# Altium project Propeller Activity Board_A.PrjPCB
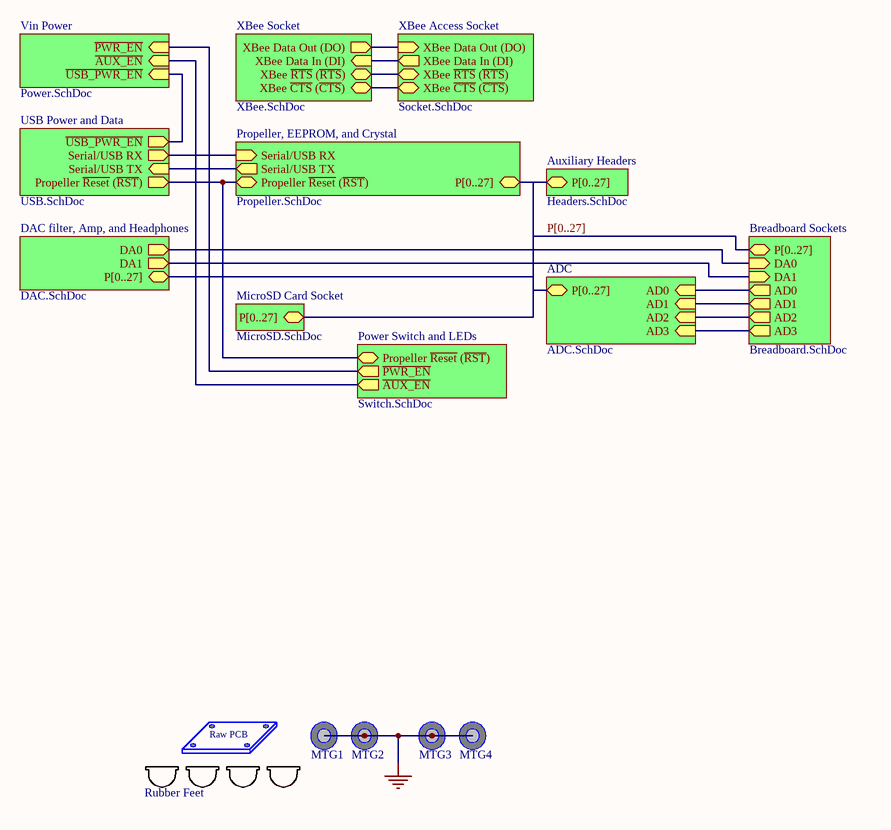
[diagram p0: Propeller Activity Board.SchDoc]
PartNumber: 32910; ProductOwner: Education; ProjectRevision: A; ProjectTitle: Propeller Activity Board
12 sheets, 110 parts. Net scope: hierarchical (ports join the sheet entries above them; power ports are global).
Board files: Propeller Activity Board_A.PcbDoc, Propeller Activity Board_A Array.PcbDoc
Sheets:
  Propeller Activity Board.SchDoc
    Propeller, EEPROM, and Crystal = Propeller.SchDoc
    Vin Power = Power.SchDoc
    Power Switch and LEDs = Switch.SchDoc
    USB Power and Data = USB.SchDoc
    DAC filter, Amp, and Headphones = DAC.SchDoc
    ADC = ADC.SchDoc
    MicroSD Card Socket = MicroSD.SchDoc
    XBee Socket = XBee.SchDoc
    Auxiliary Headers = Headers.SchDoc
    XBee Access Socket = Socket.SchDoc
    Breadboard Sockets = Breadboard.SchDoc

## Sheet Propeller Activity Board.SchDoc: PropBOE
size Letter; CompanyName: Parallax Inc.; Organization: Parallax inc.; Revision: B; SheetNumber: 1; SheetTotal: 12

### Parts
Feet1  Rubber Feet
MTG1  Screw Hole  [MTG_250R-125D]  (value not drawn)  (no BOM)
MTG2  Screw Hole  [MTG_250R-125D]  (value not drawn)  (no BOM)
MTG3  Screw Hole  [MTG_250R-125D]  (value not drawn)  (no BOM)
MTG4  Screw Hole  [MTG_250R-125D]  (value not drawn)  (no BOM)
PCB1  Raw PCB  (value not drawn)  (mechanical)

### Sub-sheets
ADC = ADC.SchDoc: AD0 (in), AD1 (in), AD2 (in), AD3 (in), P[0..27] (bidir)
Auxiliary Headers = Headers.SchDoc: P[0..27] (bidir)
Breadboard Sockets = Breadboard.SchDoc: DA0 (in), DA1 (in), P[0..27] (bidir), AD0 (out), AD1 (out), AD2 (out), AD3 (out)
DAC filter, Amp, and Headphones = DAC.SchDoc: P[0..27] (bidir), DA0 (out), DA1 (out)
MicroSD Card Socket = MicroSD.SchDoc: P[0..27] (bidir)
Power Switch and LEDs = Switch.SchDoc: ~{PWR_EN} (out), ~{AUX_EN} (out), Propeller ~{Reset} (~{RST}) (bidir)
Propeller, EEPROM, and Crystal = Propeller.SchDoc: Serial/USB RX (in), Serial/USB TX (out), P[0..27] (bidir), Propeller ~{Reset} (~{RST}) (bidir)
USB Power and Data = USB.SchDoc: Serial/USB RX (out), Serial/USB TX (in), Propeller ~{Reset} (~{RST}) (out), ~{USB_PWR_EN} (out)
Vin Power = Power.SchDoc: ~{PWR_EN} (in), ~{AUX_EN} (in), ~{USB_PWR_EN} (in)
XBee Access Socket = Socket.SchDoc: XBee ~{CTS} (~{CTS}) (bidir), XBee ~{RTS} (~{RTS}) (bidir), XBee Data In (DI) (out), XBee Data Out (DO) (in)
XBee Socket = XBee.SchDoc: XBee Data Out (DO) (out), XBee Data In (DI) (in), XBee ~{CTS} (~{CTS}) (bidir), XBee ~{RTS} (~{RTS}) (bidir)

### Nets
GND: MTG1.1 MTG2.1 MTG3.1 MTG4.1
~{AUX_EN}: sheet Vin Power/~{AUX_EN}, sheet Power Switch and LEDs/~{AUX_EN}
AD0: sheet ADC/AD0, sheet Breadboard Sockets/AD0
AD1: sheet ADC/AD1, sheet Breadboard Sockets/AD1
AD2: sheet ADC/AD2, sheet Breadboard Sockets/AD2
AD3: sheet ADC/AD3, sheet Breadboard Sockets/AD3
DA0: sheet DAC filter, Amp, and Headphones/DA0, sheet Breadboard Sockets/DA0
DA1: sheet DAC filter, Amp, and Headphones/DA1, sheet Breadboard Sockets/DA1
~{PWR_EN}: sheet Vin Power/~{PWR_EN}, sheet Power Switch and LEDs/~{PWR_EN}
Propeller ~{Reset} (~{RST}): sheet Propeller, EEPROM, and Crystal/Propeller ~{Reset} (~{RST}), sheet Power Switch and LEDs/Propeller ~{Reset} (~{RST}), sheet USB Power and Data/Propeller ~{Reset} (~{RST})
Serial/USB RX: sheet Propeller, EEPROM, and Crystal/Serial/USB RX, sheet USB Power and Data/Serial/USB RX
Serial/USB TX: sheet Propeller, EEPROM, and Crystal/Serial/USB TX, sheet USB Power and Data/Serial/USB TX
~{USB_PWR_EN}: sheet Vin Power/~{USB_PWR_EN}, sheet USB Power and Data/~{USB_PWR_EN}
XBee ~{CTS} (~{CTS}): sheet XBee Socket/XBee ~{CTS} (~{CTS}), sheet XBee Access Socket/XBee ~{CTS} (~{CTS})
XBee Data In (DI): sheet XBee Socket/XBee Data In (DI), sheet XBee Access Socket/XBee Data In (DI)
XBee Data Out (DO): sheet XBee Socket/XBee Data Out (DO), sheet XBee Access Socket/XBee Data Out (DO)
XBee ~{RTS} (~{RTS}): sheet XBee Socket/XBee ~{RTS} (~{RTS}), sheet XBee Access Socket/XBee ~{RTS} (~{RTS})

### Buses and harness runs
bus P[0..27] = sheet ADC/P[0..27] = sheet Auxiliary Headers/P[0..27] = sheet Breadboard Sockets/P[0..27] = sheet DAC filter, Amp, and Headphones/P[0..27] = sheet MicroSD Card Socket/P[0..27] = sheet Propeller, EEPROM, and Crystal/P[0..27]

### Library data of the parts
Feet1 = Rubber Feet: Rubber feet, 4; Manufacturer_PN: SJ-5003 (BLACK); Parallax_PN: 700-00037; Syspro_Desc: PCB Feet, Rubber
MTG1-MTG4 = Screw_Hole: Screw hole for mounting (or high-current connection)
PCB1 = Raw PCB: Raw PCB (For BOM purposes); Parallax_PN: 300-32910; Syspro_Desc: PCB,Raw,Propeller Activity Bd

## Sheet Propeller.SchDoc
size Letter; SheetNumber: 9; SheetTotal: 14
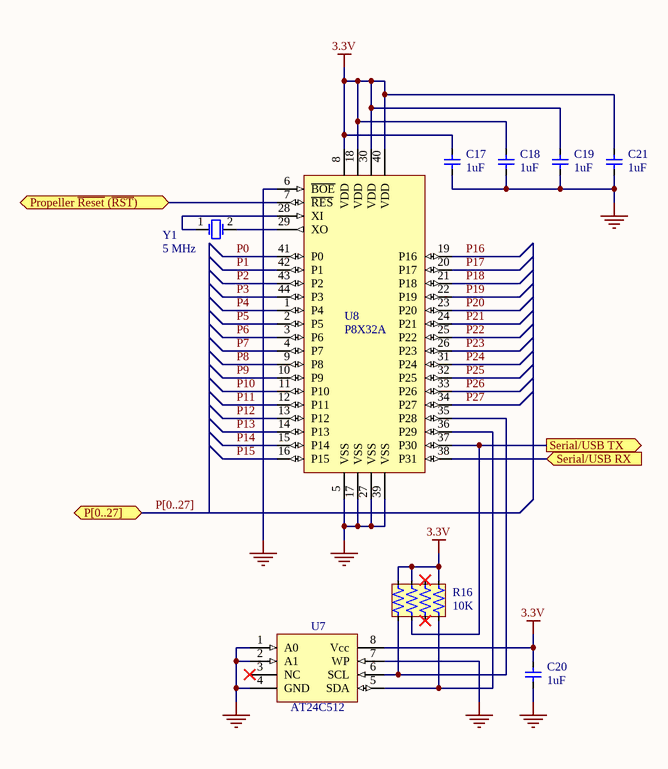
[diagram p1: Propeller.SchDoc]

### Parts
C17  value 1uF  [R/C_0402(1005)]
C18  value 1uF  [R/C_0402(1005)]
C19  value 1uF  [R/C_0402(1005)]
C20  value 1uF  [R/C_0402(1005)]
C21  value 1uF  [R/C_0402(1005)]
R16  value 10K  [R_ARRAY-0402x4]  (hidden comment: Res_Net)
U7  AT24C512  [U_AT24C512K]
U8  P8X32A  [U_P8X32A-Q44]
Y1  value 5 MHz  [Y_HC-49US]  (hidden comment: XTAL)

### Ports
P[0..27] (bidir), Propeller ~{Reset} (~{RST}) (bidir), Serial/USB RX (in), Serial/USB TX (out)

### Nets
3.3V: C17.2 C18.2 C19.2 C20.2 C21.2 R16.1 R16.3 R16.4 U7.8(Vcc) U8.8(VDD) U8.18(VDD) U8.30(VDD) U8.40(VDD)
GND: C17.1 C18.1 C19.1 C20.1 C21.1 U7.1(A0) U7.2(A1) U7.4(GND) U7.7(WP) U8.5(VSS) U8.6(~{BOE}) U8.17(VSS) U8.27(VSS) U8.39(VSS)
P0: U8.41(P0)
P1: U8.42(P1)
P2: U8.43(P2)
P3: U8.44(P3)
P4: U8.1(P4)
P5: U8.2(P5)
P6: U8.3(P6)
P7: U8.4(P7)
P8: U8.9(P8)
P9: U8.10(P9)
P10: U8.11(P10)
P11: U8.12(P11)
P12: U8.13(P12)
P13: U8.14(P13)
P14: U8.15(P14)
P15: U8.16(P15)
P16: U8.19(P16)
P17: U8.20(P17)
P18: U8.21(P18)
P19: U8.22(P19)
P20: U8.23(P20)
P21: U8.24(P21)
P22: U8.25(P22)
P23: U8.26(P23)
P24: U8.31(P24)
P25: U8.32(P25)
P26: U8.33(P26)
P27: U8.34(P27)
Propeller ~{Reset} (~{RST}): U8.7(~{RES}) ; port Propeller ~{Reset} (~{RST})
Serial/USB RX: U8.38(P31) ; port Serial/USB RX
Serial/USB TX: R16.6 U8.37(P30) ; port Serial/USB TX
NetR16_5: R16.5 U7.6(SCL) U8.35(P28)
NetR16_8: R16.8 U7.5(SDA) U8.36(P29)
NetU8_28: U8.28(XI) Y1.1(OSC1)
NetU8_29: U8.29(XO) Y1.2(OSC2)

Not connected (* = marked no-connect by the designer): R16 2* 7*; U7 3(NC)*

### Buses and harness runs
bus P[0..27] = port P[0..27]

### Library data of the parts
C17-C21 = Capacitor: Cap, 1uF, 0402, X5R; Manufacturer_PN: C1005X5R1A105M050BB; Syspro_Desc: CAP-CER,1.0uF,X5R,10V,0402; Parallax_PN: 200-11511
R16 = Res_Net: Resistor Network; Manufacturer_PN: RAVF104DJT10K0; Syspro_Desc: RES-NTWK,10K,5%,0804; Parallax_PN: 179-10000
U7 = AT24C512: 512K (65,536 x 8) I2C EEPROM; Manufacturer: Paralax Inc.; Manufacturer_PN: M24512-RDW6TP; Est_Cost: 1.025; Parallax_PN: 602-10001; MaxOpTempC: 125; MinOpTempC: -55; Syspro_Desc: IC SRL EEPROM 512K 2.7V
U8 = P8X32A-Q44: Manufacturer: Paralax Inc.; Est_Cost: 2.29216; MaxOpTempC: 125; MinOpTempC: -55; Syspro_Desc: IC-P8X32A-Q44 (QFP)
Y1 = XTAL: Crystal Oscillator; Manufacturer_PN: ECS-50-20-4X; Parallax_PN: 251-05000; Syspro_Desc: XTAL,HC-49US,5MHz,20pF,TH

## Sheet Power.SchDoc
size Letter; SheetNumber: 8; SheetTotal: 14; PageSetup: Record=PageOptions|CenterHorizontal=True|CenterVertical=True|PrintScale=0.98|XCorrection=1.00|YCorrection=1.00|PrintKind=1|BorderSize=5000000|LeftOffset=0|BottomOffset=0|Orientation=2|PaperLength=1000|PaperWidth=1000|Scale=100|PaperSource=7|PrintQuality=-4|MediaType=1|DitherType=10|PaperKind=Letter|PrintScaleMode=1
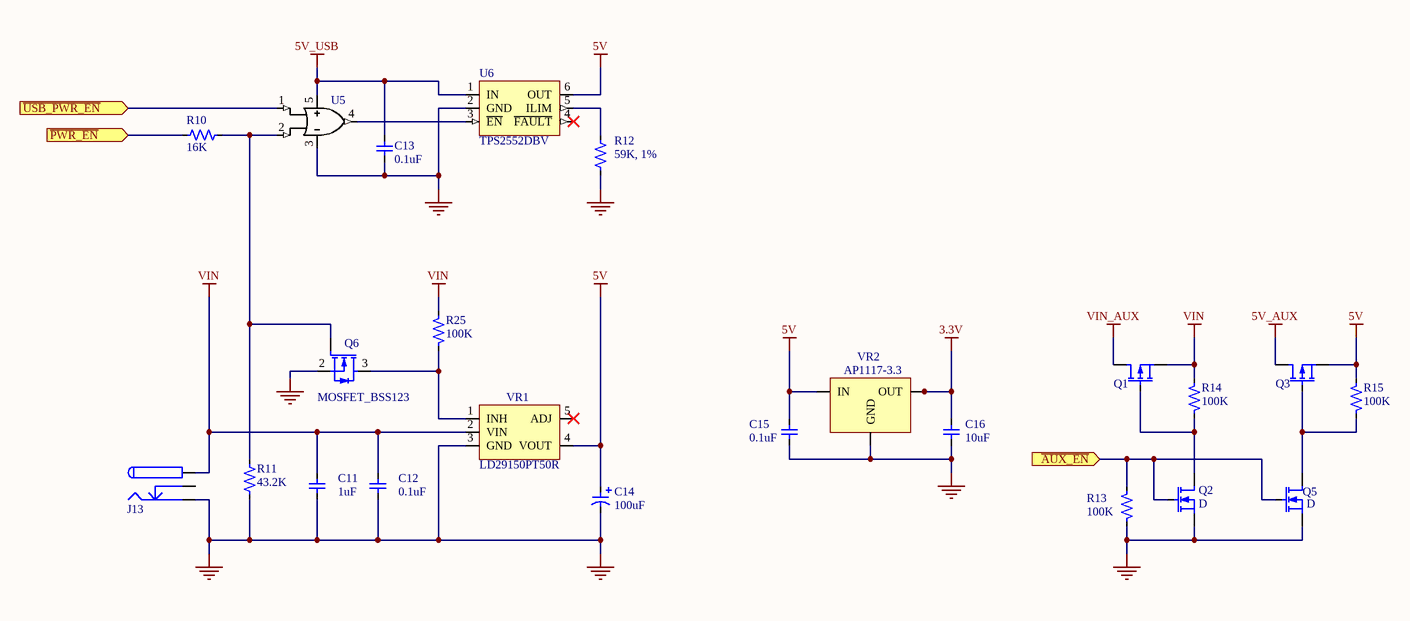
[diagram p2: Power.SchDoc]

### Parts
C11  value 1uF  [R/C_0402(1005)]  (hidden comment: Capacitor)
C12  value 0.1uF  [R/C_0402(1005)]  (hidden comment: Capacitor)
C13  value 0.1uF  [R/C_0603(1608)]  (hidden comment: Capacitor)
C14  value 100uF  [C_6.3x7.7_25V-ALUM]  (hidden comment: Cap_Pol)
C15  value 0.1uF  [R/C_0603(1608)]  (hidden comment: Capacitor)
C16  value 10uF  [R/C_0805(2012)]  (hidden comment: Capacitor)
J13  PWR2.1  [J_CON 2.1mm PWR]  (value not drawn)
Q1  D  [Q_SOT23]  (value not drawn)
Q2  D  [Q_SOT23]
Q3  D  [Q_SOT23]  (value not drawn)
Q5  D  [Q_SOT23]
Q6  MOSFET_BSS123  [Q_SOT23]
R10  value 16K  [R/C_0402(1005)]  (hidden comment: Resistor)
R11  value 43.2K  [R/C_0402(1005)]  (hidden comment: Resistor)
R12  value 59K, 1%  [R/C_0402(1005)]  (hidden comment: Resistor)
R13  value 100K  [R/C_0402(1005)]  (hidden comment: Resistor)
R14  value 100K  [R/C_0402(1005)]  (hidden comment: Resistor)
R15  value 100K  [R/C_0402(1005)]  (hidden comment: Resistor)
R25  value 100K  [R/C_0402(1005)]  (hidden comment: Resistor)
U5  74LVC1G32  [SOT323-5L]  (value not drawn)
U6  TPS2552DBV  [U_TPS2553DBVT]
VR1  LD29150PT50R  [VR_PPAK]
VR2  AP1117-3.3  [VR_SOT223]

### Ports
~{AUX_EN} (in), ~{PWR_EN} (in), ~{USB_PWR_EN} (in)

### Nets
3.3V: C16.2 VR2.OUT_1(OUT) VR2.OUT_2(OUT)
5V: C14.1(Positive) C15.1 Q3.2(Source) R15.2 U6.6(OUT) VR1.4(VOUT) VR2.IN
5V_AUX: Q3.3(Drain)
5V_USB: C13.1 U5.5(VCC) U6.1(IN)
GND: C11.2 C12.2 C13.2 C14.2(Negative) C15.2 C16.1 J13.- Q2.2(Source) Q5.2(Source) Q6.2(S) R11.1 R12.1 R13.1 U5.3(GND) U6.2(GND) VR1.3(GND) VR2.GND
VIN: C11.1 C12.1 J13.+ Q1.2(Source) R14.1 R25.1 VR1.2(VIN)
VIN_AUX: Q1.3(Drain)
~{AUX_EN}: Q2.1(Gate) Q5.1(Gate) R13.2 ; port ~{AUX_EN}
~{PWR_EN}: R10.2 ; port ~{PWR_EN}
~{USB_PWR_EN}: U5.1(A) ; port ~{USB_PWR_EN}
NetQ1_1: Q1.1(Gate) Q2.3(Drain) R14.2
NetQ3_1: Q3.1(Gate) Q5.3(Drain) R15.1
NetQ6_1: Q6.1(G) R10.1 R11.2 U5.2(B)
NetQ6_3: Q6.3(D) R25.2 VR1.1(INH)
NetR12_2: R12.2 U6.5(ILIM)
NetU5_4: U5.4(Y) U6.3(~{EN})

Not connected (* = marked no-connect by the designer): J13 S; U6 4(~{FAULT})*; VR1 5(ADJ)*

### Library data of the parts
C11 = Capacitor: Manufacturer_PN: C1005X5R1A105M050BB; Syspro_Desc: CAP-CER,1.0uF,X5R,10V,0402; Parallax_PN: 200-11511
C12 = Capacitor: Manufacturer_PN: CC0402ZRY5V8BB104; Syspro_Desc: CAP-CER,0.1uF,Y5R,25V,0402; Parallax_PN: 200-11509
C13 C15 = Capacitor: Manufacturer_PN: GRM188F51E104ZA01D; Syspro_Desc: CAP-CER,0.1uF,20%,25V,Y5V,0603; Parallax_PN: 213-01040
C14 = Cap_Pol: Polarized Capacitor; Manufacturer_PN: EMVA250ADA101MF80G; Syspro_Desc: CAP-ALUM,100uF,25V,20%,6.3mm; Parallax_PN: 200-11518
C16 = Capacitor: Manufacturer_PN: C2012Y5V1C106Z; Est_Cost: 0.02843; Syspro_Desc: CAP-CER,10uF,16V,0805; Parallax_PN: 200-11503
J13 = PWR2.1: Low Voltage Power Supply Connector; Manufacturer: Paralax Inc.; Manufacturer_PN: RAPC722X; Parallax_PN: 452-00007; Est_Cost: 0.6822; Syspro_Desc: Connector, PWR, 2.1mm
Q1 Q3 = MOSFET-P: MOSFET P-ch; Manufacturer_PN: DMP2305U; Syspro_Desc: MOSFET,P-CH,20V,4.2A,SOT-23; Parallax_PN: 500-10025
Q2 Q5 = MOSFET-N: MOSFET N-ch; Manufacturer_PN: 2N7002-TP; Syspro_Desc: FET-NCH,60V,115mA,SOT-23; Parallax_PN: 500-10015
Q6 = MOSFET-N DUAL: BSS123; Manufacturer_PN: 74LVC1G58GW,125; Parallax_PN: 500-10016; Syspro_Desc: IC-MOSFET, BSS123, SOT-23
R10 = Resistor: Manufacturer_PN: ERJ-2GEJ163X; Syspro_Desc: RES,16k,5%,0402; Parallax_PN: 150-12022
R11 = Resistor: Manufacturer_PN: RC0402FR-0743K2L; Syspro_Desc: RES,43.2K,1%,0402; Parallax_PN: 172-16007
R12 = Resistor: Manufacturer_PN: RMCF0402FT59K0; Syspro_Desc: RES,59k,1%,0402; Parallax_PN: 172-16005
R13-R15 R25 = Resistor: Manufacturer_PN: RMCF0402JT100K; Syspro_Desc: RES,100K,5%,0402; Parallax_PN: 173-01040
U5 = 74LVC1G32: OR gate; Manufacturer: Any; Est_Cost: 0.0801; Parallax_PN: 604-10026; MaxOpTempC: 125; MinOpTempC: -40; Syspro_Desc: IC-SNGL 2-INPT,OR GATE,SOT-353
U6 = TPS2552DBVR: Current-limited Power-distribution Switch; Manufacturer: Texas Instruments Inc.; Est_Cost: 1.28; Parallax_PN: 400-10008; MaxOpTempC: 150; MinOpTempC: -40; Syspro_Desc: IC-PWR DIST SWITCH,ADJ,SOT23-6
VR1 = VR_LD29150: Parallax_PN: 601-00523; Syspro_Desc: IC REG LDO 5V 1.5A PPAK
VR2 = AP1117-3.3: 3.3V 1A LDO; pin to pad: GND>1 IN>3 OUT_1>2 OUT_2>4; Manufacturer: Any; Est_Cost: 0.1558; Parallax_PN: 601-10504; MaxOpTempC: 125; MinOpTempC: 0; Syspro_Desc: IC-REG,LDO,1.0A,3.3V,SOT-223

## Sheet Switch.SchDoc
size Letter; SheetNumber: 11; SheetTotal: 14
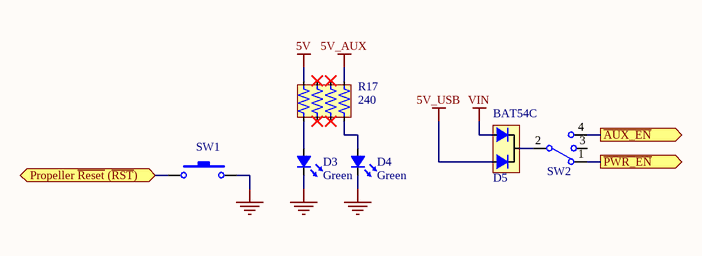
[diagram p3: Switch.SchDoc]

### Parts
D3  Color: Green  [D_LED1608-0603]  (hidden comment: LED)
D4  Color: Green  [D_LED1608-0603]  (hidden comment: LED)
D5  Manufacturer_PN: BAT54C  [Q_SOT23]  (hidden comment: Diode Pair, CC)
R17  value 240  [R_ARRAY-0402x4]  (hidden comment: Res_Net)
SW1  SW-PB  [SW_SMD_J-bend]  (value not drawn)
SW2  Power selection switch  [SWI_OS103011MS8QP1]  (value not drawn)

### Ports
Propeller ~{Reset} (~{RST}) (bidir), ~{AUX_EN} (out), ~{PWR_EN} (out)

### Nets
5V: R17.4
5V_AUX: R17.1
5V_USB: D5.2(Anode)
GND: D3.2(Cathode) D4.2(Cathode) SW1.2
VIN: D5.1(Anode)
~{AUX_EN}: SW2.4(NC2) ; port ~{AUX_EN}
~{PWR_EN}: SW2.1(NC1) ; port ~{PWR_EN}
Propeller ~{Reset} (~{RST}): SW1.1 ; port Propeller ~{Reset} (~{RST})
NetD3_1: D3.1(Anode) R17.5
NetD4_1: D4.1(Anode) R17.8
NetD5_3: D5.3(Cathode) SW2.2(COMMON1)

Not connected (* = marked no-connect by the designer): R17 2* 3* 6* 7*; SW2 3(NO1)

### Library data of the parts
D3 D4 = LED: Manufacturer_PN: LTST-C191KGKT; Parallax_PN: 350-10003; Syspro_Desc: LED 0603, Green Clear; Rotation_Offset: 180
D5 = Diode_Pair_CC: Diode Pair, Common Cathode; Syspro_Desc: DIO-CC,BAT54C,200mA,30V; Parallax_PN: 501-10023; Rotation_Offset: 90
R17 = Res_Net: Resistor Network; Manufacturer_PN: CRA4S8240TR-ND; Syspro_Desc: RES-NTWK,240,5%,0804; Parallax_PN: 179-10006
SW1 = SW-PB: Push-button switch; Manufacturer: C&K Components; Manufacturer_PN: PTS645SM43SMTR LFS; Parallax_PN: 400-10002; Syspro_Desc: SW-PB,Tactile,Blue,SMD; Est_Cost: 0.137; Rotation_Offset: 0
SW2 = SW-SP3T: Switch SP3T; Manufacturer: C&K Components; Manufacturer_PN: 611-OS103011MS8QP1; Est_Cost: 0.249; Parallax_PN: 400-10007; Syspro_Desc: SWI,SP3T Slide,0.1A,12V,TH

## Sheet USB.SchDoc
size Letter; DrawnBy: T.B.; SheetNumber: 3; SheetTotal: 5; DocumentDescription: Schematic, USB Connection; SheetSize: Letter; ProjectRevision: A; ProjectDescription: Propeller Activity Board; ProjectTitle: Propeller Activity Board; PartNumber: 32910
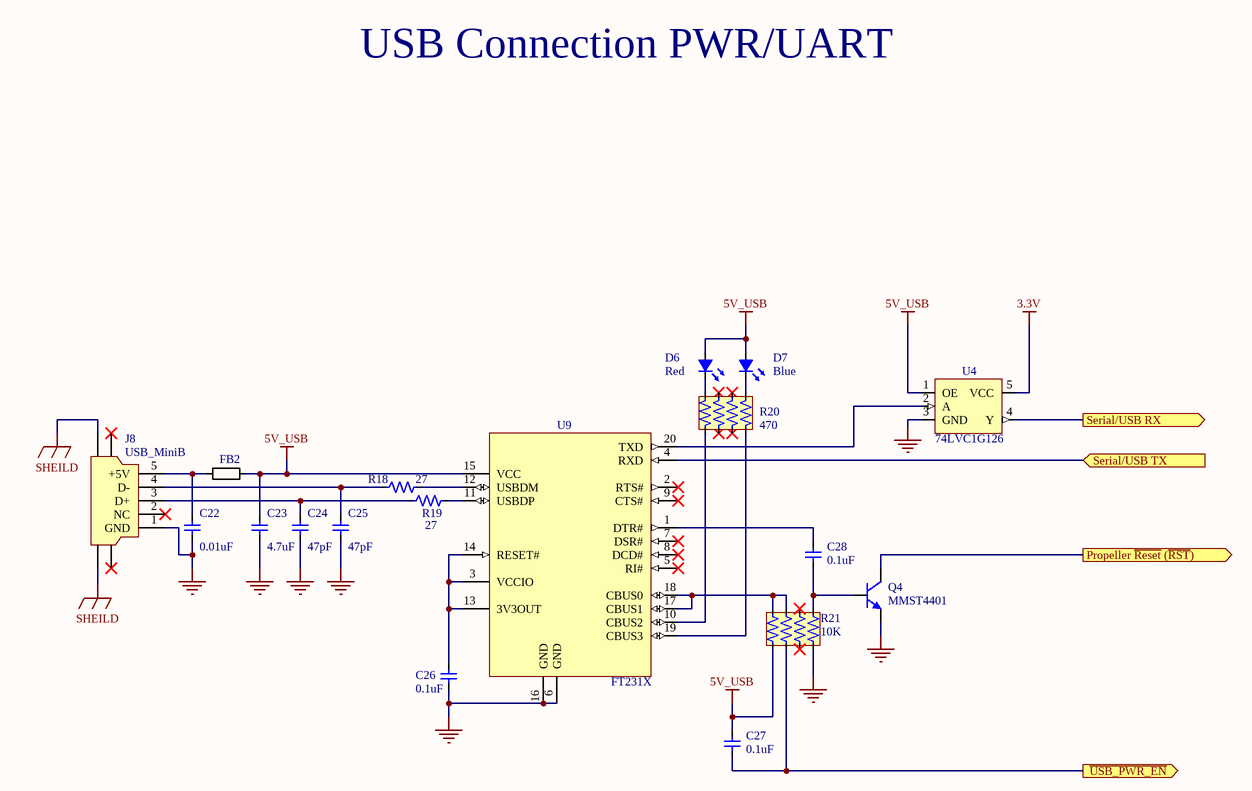
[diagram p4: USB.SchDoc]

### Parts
C22  value 0.01uF  [R/C_0603(1608)]  (hidden comment: Capacitor)
C23  value 4.7uF  [R/C_0603(1608)]  (hidden comment: Capacitor)
C24  value 47pF  [R/C_0603(1608)]  (hidden comment: Capacitor)
C25  value 47pF  [R/C_0603(1608)]  (hidden comment: Capacitor)
C26  value 0.1uF  [R/C_0603(1608)]  (hidden comment: Capacitor)
C27  value 0.1uF  [R/C_0603(1608)]
C28  value 0.1uF  [R/C_0603(1608)]  (hidden comment: Capacitor)
D6  Color: Red  [LED1608-0603]  (hidden comment: LED)
D7  Color: Blue  [LED1608-0603]  (hidden comment: LED)
FB2  Ferrite Bead  [CD1608-0603]  (value not drawn)
J8  USB_MiniB  [J_USB MINI B-TH_SD-51387-3]
Q4  Manufacturer_PN: MMST4401  [Q_SOT323]  (hidden comment: BJT_NPN)
R18  value 27  [R/C_0603(1608)]  (hidden comment: Resistor)
R19  value 27  [R/C_0603(1608)]  (hidden comment: Resistor)
R20  value 470  [R_ARRAY-0402x4]  (hidden comment: Res_Net)
R21  value 10K  [R_ARRAY-0402x4]  (hidden comment: Res_Net)
U4  74LVC1G126  [SOT353-5AN]
U9  FT231X  [U_SSOP20_FT231XS]

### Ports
Propeller ~{Reset} (~{RST}) (out), Serial/USB RX (out), Serial/USB TX (in), ~{USB_PWR_EN} (out)

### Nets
3.3V: U4.5(VCC)
5V_USB: C23.2 C27.2 D6.A(Anode) D7.A(Anode) FB2.1 R21.5 U4.1(OE) U9.15(VCC)
GND: C22.1 C23.1 C24.1 C25.1 C26.1 J8.1(GND) Q4.E(Emitter) R21.8 U4.3(GND) U9.6(GND) U9.16(GND)
SHEILD: J8.7(Sh) J8.8(Sh)
Propeller ~{Reset} (~{RST}): Q4.C(Collector) ; port Propeller ~{Reset} (~{RST})
Serial/USB RX: U4.4(Y) ; port Serial/USB RX
Serial/USB TX: U9.4(RXD) ; port Serial/USB TX
~{USB_PWR_EN}: C27.1 R21.6 ; port ~{USB_PWR_EN}
NetC22_2: C22.2 FB2.2 J8.5(+5V)
NetC24_2: C24.2 J8.3(D+) R19.2
NetC25_2: C25.2 J8.4(D-) R18.2
NetC26_2: C26.2 U9.3(VCCIO) U9.13(3V3OUT) U9.14(RESET#)
NetC28_1: C28.1 Q4.B(Base) R21.1
NetC28_2: C28.2 U9.1(DTR#)
NetD6_K: D6.K(Cathode) R20.5
NetD7_K: D7.K(Cathode) R20.8
NetR18_1: R18.1 U9.12(USBDM)
NetR19_1: R19.1 U9.11(USBDP)
NetR20_1: R20.1 U9.19(CBUS3)
NetR20_4: R20.4 U9.10(CBUS2)
NetR21_3: R21.3 R21.4 U9.17(CBUS1) U9.18(CBUS0)
NetU4_2: U4.2(A) U9.20(TXD)

Not connected (* = marked no-connect by the designer): J8 2(NC)* 6(Sh)* 9(Sh)*; R20 2* 3* 6* 7*; R21 2* 7*; U9 2(RTS#)* 5(RI#)* 7(DSR#)* 8(DCD#)* 9(CTS#)*

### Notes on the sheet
- USB Connection PWR/UART

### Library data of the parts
C22 = Capacitor: Manufacturer: Generic; Manufacturer_PN: C0603C103K5RACTU; Est_Cost: 0.005; Syspro_Desc: CAP-CER,0.01uF,10%,50V,X7R,060; Parallax_PN: 213-01041
C23 = Capacitor: Manufacturer_PN: GRM188F51A475ZE20D; Syspro_Desc: CAP-CER,4.7uF,20%,6.3V,0603; Parallax_PN: 213-04761
C24 C25 = Capacitor: Manufacturer_PN: C1608C0G1H470J080AA; Syspro_Desc: CAP-CER,47pF,25V,0603; Parallax_PN: 200-11532
C26 = Capacitor: Manufacturer: Generic; Manufacturer_PN: C0603C104K4RACTU; Est_Cost: 0.005; Syspro_Desc: CAP-CER,0.1uF,10%,16V,X7R,0603; Parallax_PN: 200-11041
C27 = Capacitor: Manufacturer_PN: CC0402ZRY5V8BB104; Syspro_Desc: CAP-CER,0.1uF,20%,25V,Y5V,0603; Parallax_PN: 213-01040
C28 = Capacitor: Manufacturer_PN: CC0402ZRY5V8BB104; Parallax_PN: 213-01040; Syspro_Desc: CAP-CER,0.1uF,20%,25V,Y5V,0603
D6 = LED: Manufacturer_PN: LTST-C191KRKT; Parallax_PN: 350-10001; Syspro_Desc: LED 0603, Super Red Clear
D7 = LED: Manufacturer_PN: APT1608QBC/D; Parallax_PN: 350-10004; Syspro_Desc: LED 0603, Blue Clear
FB2 = Ferrite Bead: Manufacturer_PN: MPZ1608S221A; Est_Cost: .04; Parallax_PN: 275-10004; Syspro_Desc: Ferrite Bead,2A,22OHM,0603,SMT
J8 = USB_MiniB: USB Mini B; Manufacturer_PN: 0513870578; Parallax_PN: 452-10020; Syspro_Desc: CON,USB Mini-B,SMD+TH
Q4 = BJT_NPN: NPN Bipolar Transistor; pin to pad: B>1 C>3 E>2; Manufacturer: Micro Commercial Co; Est_Cost: 0.054; Parallax_PN: 500-10000; Syspro_Desc: XSTR-NPN,SW,40V,SOT-323
R18 R19 = Resistor: Manufacturer_PN: ERJ-3GEYJ270V; Est_Cost: 0.001; Syspro_Desc: RES,27,5%,0603; Parallax_PN: 150-11038
R20 = Res_Net: Resistor Network; Manufacturer_PN: RAVF104DJT470R; Syspro_Desc: RES-NTWK,470,5%,0804; Parallax_PN: 179-10008
R21 = Res_Net: as R16 on sheet Propeller
U4 = 74LVC1G126: 1-bit Buffer with Enable, Non-inv; Manufacturer: Any; Manufacturer_PN: 74LVC1G126SE-7; Est_Cost: 0.06; Syspro_Desc: IC,1xBuffer w/En,N-inv; Parallax_PN: 603-10010
U9 = FT231X: USB UART; Manufacture_PN: FT231XS-R; Parallax_PN: 604-00065; Syspro_Desc: IC-FTDI, FT231X; Est_Cost: 1.20

## Sheet DAC.SchDoc
size Letter; SheetNumber: 4; SheetTotal: 14
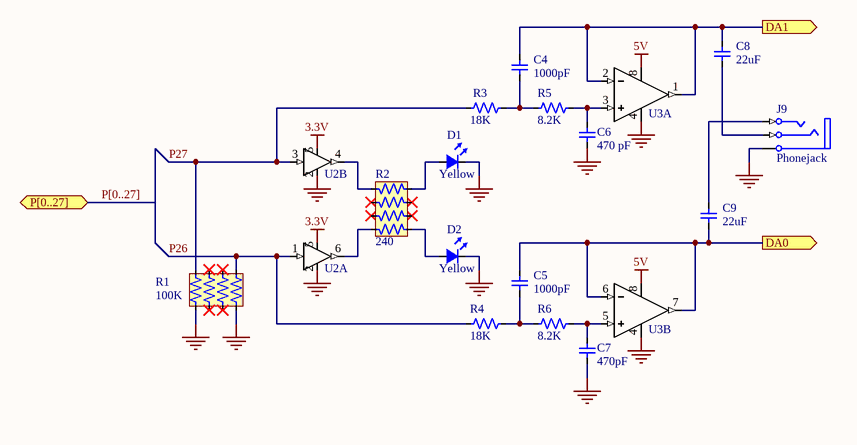
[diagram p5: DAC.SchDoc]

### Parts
C4  value 1000pF  [R/C_0402(1005)]  (hidden comment: Capacitor)
C5  value 1000pF  [R/C_0402(1005)]  (hidden comment: Capacitor)
C6  value 470 pF  [R/C_0402(1005)]  (hidden comment: Capacitor)
C7  value 470pF  [R/C_0402(1005)]  (hidden comment: Capacitor)
C8  value 22uF  [R/C_0805(2012)]  (hidden comment: Capacitor)
C9  value 22uF  [R/C_0805(2012)]  (hidden comment: Capacitor)
D1  Color: Yellow  [LED1608-0603]  (hidden comment: LED)
D2  Color: Yellow  [LED1608-0603]  (hidden comment: LED)
J9  Phonejack
R1  value 100K  [R_ARRAY-0402x4]  (hidden comment: Res_Net)
R2  value 240  [R_ARRAY-0402x4]  (hidden comment: Res_Net)
R3  value 18K  [R/C_0402(1005)]  (hidden comment: Resistor)
R4  value 18K  [R/C_0402(1005)]  (hidden comment: Resistor)
R5  value 8.2K  [R/C_0402(1005)]  (hidden comment: Resistor)
R6  value 8.2K  [R/C_0402(1005)]  (hidden comment: Resistor)
U2  NC7WZ17  [SOT363-6L]  (value not drawn)  (parts A,B of 2)
U3  TSV912  [SOIC127P600-8M]  (value not drawn)  (parts A,B of 2)

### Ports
DA0 (out), DA1 (out), P[0..27] (bidir)

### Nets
3.3V: U2.5(Vcc)
5V: U3.8(DCD#)
GND: C6.1 C7.1 D1.2(Cathode) D2.2(Cathode) J9.1(Sleeve) R1.5 R1.8 U2.2(GND) U3.4(RXD)
DA0: C5.2 C9.1 U3.6(GND) U3.7(DSR#) ; port DA0
DA1: C4.2 C8.2 U3.1(DTR#) U3.2(RTS#) ; port DA1
P26: R1.1 R4.2 U2.1(A)
P27: R1.4 R3.2 U2.3(A)
NetC4_1: C4.1 R3.1 R5.2
NetC5_1: C5.1 R4.1 R6.2
NetC6_2: C6.2 R5.1 U3.3(VCCIO)
NetC7_2: C7.2 R6.1 U3.5(RI#)
NetC8_1: C8.1 J9.3(Ring)
NetC9_2: C9.2 J9.2(Tip)
NetD1_1: D1.1(Anode) R2.1
NetD2_1: D2.1(Anode) R2.4
NetR2_5: R2.5 U2.6(Y)
NetR2_8: R2.8 U2.4(Y)

Not connected (* = marked no-connect by the designer): R1 2* 3* 6* 7*; R2 2* 3* 6* 7*

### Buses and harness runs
bus P[0..27] = port P[0..27]

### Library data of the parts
C4 C5 = Capacitor: Manufacturer_PN: 04025C102JAT2A; Parallax_PN: 200-10503; Syspro_Desc: CAP-CER,1000pF,5%,50V
C6 C7 = Capacitor: Manufacturer_PN: CC0402KRX7R9BB471; Parallax_PN: 200-10502; Syspro_Desc: CAP-CER,470pF,10%,50V
C8 C9 = Capacitor: Manufacturer_PN: C2012X5R1A226M125AB; Parallax_PN: 200-11507; Syspro_Desc: CAP-CER,22uF,10V,X5R,0805
D1 D2 = LED: Manufacturer_PN: LTST-C191KSKT; Parallax_PN: 350-10002; Syspro_Desc: LED 0603, Yellow Clear
J9 = Phonejack: Jack Socket, 1/8" [6.5mm], Thru-Hole, Vertical, 3-Conductor Open Circuit (Non-Normalling); Manufacturer_PN: SJ-3523-SMT-TR; Manufacturer: CUI Inc; Parallax_PN: 452-10018; Syspro_Desc: CON-JACK,STEREO,RA,3.5mm
R1 = Res_Net: Resistor Network; Manufacturer_PN: RAVF104DJT100K; Syspro_Desc: RES-NTWK,100k,5%,0804; Parallax_PN: 179-10007
R2 = Res_Net: as R17 on sheet Switch
R3 R4 = Resistor: Manufacturer_PN: RC0402FR-0718KL; Syspro_Desc: RES,18k,1%,0402; Parallax_PN: 172-16001
R5 R6 = Resistor: Manufacturer_PN: ERJ-3EKF8201V; Parallax_PN: 172-16000; Syspro_Desc: RES,8.2k,1%,0402
U2 = NC7WZ17: 2-bit Schmitt Trigger Buffer; Manufacturer_PN: NC7WZ17P6X; Manufacturer: Fairchild Semiconductor; Est_Cost: 0.08736; MaxOpTempC: 85; MinOpTempC: -40; Syspro_Desc: IC,NC7WZ16,SC-70; Parallax_PN: 603-10014
U3 = LMV358: Rail-to-Rail Ap-Amp, 2.7 to 5.5 V, 1 MHZ GBWP; Manufacturer_PN: TSV912IDT; Manufacturer: STMicroelectronics; Est_Cost: 0.428; Parallax_PN: 603-10016; MaxOpTempC: 150; MinOpTempC: -65; Syspro_Desc: IC-OPAMP,R-R,DUAL,1MHZ,SOIC-8

## Sheet ADC.SchDoc
size Letter; SheetNumber: 2; SheetTotal: 14
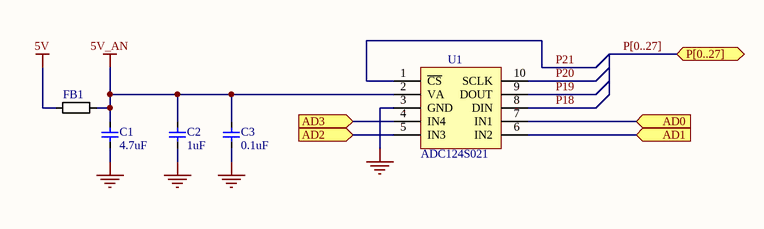
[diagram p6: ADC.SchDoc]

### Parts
C1  value 4.7uF  [R/C_0603(1608)]  (hidden comment: Capacitor)
C2  value 1uF  [C_1005N]  (hidden comment: Capacitor)
C3  value 0.1uF  [C_1005N]  (hidden comment: Capacitor)
FB1  Value: 220 Ohm @ 100MHz, 50 m Ohm DC  [CD1608-0603]  (value not drawn)
U1  ADC124S021  [U_MSSOP10]

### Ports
AD0 (in), AD1 (in), AD2 (in), AD3 (in), P[0..27] (bidir)

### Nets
5V: FB1.1
5V_AN: C1.1 C2.1 C3.2 FB1.2 U1.2(VA)
GND: C1.2 C2.2 C3.1 U1.3(GND)
AD0: U1.7(IN1) ; port AD0
AD1: U1.6(IN2) ; port AD1
AD2: U1.5(IN3) ; port AD2
AD3: U1.4(IN4) ; port AD3
P18: U1.8(DIN)
P19: U1.9(DOUT)
P20: U1.10(SCLK)
P21: U1.1(~{CS})

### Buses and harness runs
bus P[0..27] = port P[0..27]

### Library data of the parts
C1 = Capacitor: Manufacturer_PN: GRM188F51A475ZE20D; Est_Cost: 0.01721; Parallax_PN: 213-04761; Syspro_Desc: CAP-CER,4.7uF,20%,6.3V,0603
C2 = Capacitor: Manufacturer_PN: C1005X5R1A105M050BB; Parallax_PN: 200-11511; Syspro_Desc: CAP-CER,1.0uF,X5R,10V,0402
C3 = Capacitor: Manufacturer_PN: CC0402ZRY5V8BB104; Parallax_PN: 200-11509; Syspro_Desc: CAP-CER,0.1uF,Y5R,25V,0402
FB1 = Ferrite Bead: Manufacturer_PN: MPZ1608S221A; Parallax_PN: 275-10004; Syspro_Desc: Ferrite Bead,2A,22OHM,0603,SMT
U1 = U_ADC124S021: Manufacturer_PN: ADC124S021CIMM/NOPB; Parallax_PN: 604-10014; Syspro_Desc: IC-ADC,12BIT,4CH,200K,MSOP-10

## Sheet MicroSD.SchDoc
size Letter; SheetNumber: 7; SheetTotal: 14
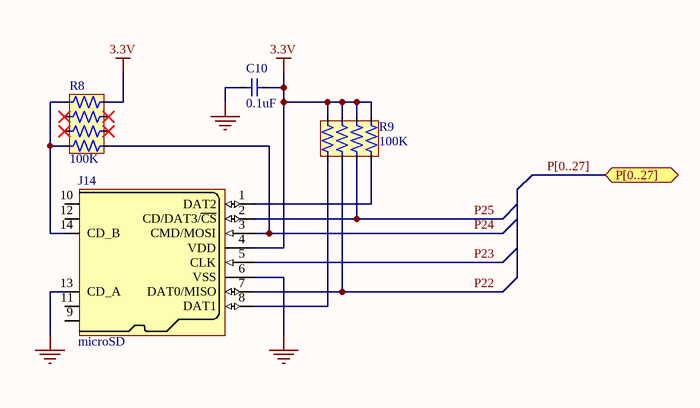
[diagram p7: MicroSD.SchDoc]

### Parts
C10  value 0.1uF  [R/C_0402(1005)]  (hidden comment: Capacitor)
J14  microSD  [J_SCKT_DM3D-SF]
R8  value 100K  [R_ARRAY-0402x4]  (hidden comment: Res_Net)
R9  value 100K  [R_ARRAY-0402x4]  (hidden comment: Res_Net)

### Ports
P[0..27] (bidir)

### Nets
3.3V: C10.1 J14.4(VDD) R8.8 R9.1 R9.2 R9.3 R9.4
GND: C10.2 J14.6(VSS) J14.13(CD_A)
P22: J14.7(DAT0/MISO) R9.6
P23: J14.5(CLK)
P24: J14.3(CMD/MOSI) R8.5
P25: J14.2(CD/DAT3/~{CS}) R9.7
NetJ14_1: J14.1(DAT2) R9.8
NetJ14_8: J14.8(DAT1) R9.5
NetJ14_14: J14.14(CD_B) R8.1 R8.4

Not connected (* = marked no-connect by the designer): J14 9 10 11 12; R8 2* 3* 6* 7*

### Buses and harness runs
bus P[0..27] = port P[0..27]

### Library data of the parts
C10 = Capacitor: Standard Filter Cap; Manufacturer_PN: CC0402ZRY5V8BB104; Parallax_PN: 200-11509; Syspro_Desc: CAP-CER,0.1uF,Y5R,25V,0402
J14 = DM3D-SF: Est_Cost: 0.75; Parallax_PN: 452-10017; Syspro_Desc: CON-MICRO SD,RA,PUSH-PULL,SMT
R8 R9 = Res_Net: as R1 on sheet DAC

## Sheet XBee.SchDoc
size Letter; SheetNumber: 14; SheetTotal: 14
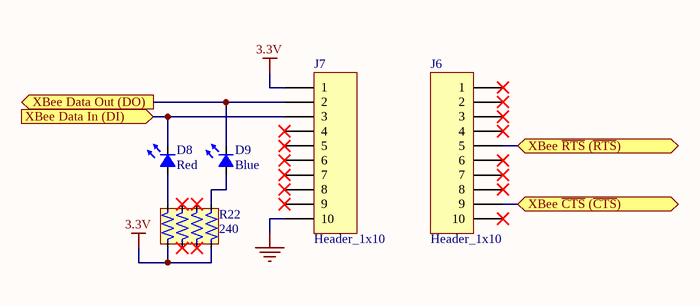
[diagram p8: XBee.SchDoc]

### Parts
D8  Color: Red  [D_LED1608-0603]  (hidden comment: LED)
D9  Color: Blue  [D_LED1608-0603]  (hidden comment: LED)
J6  Header_1x10  [J_HDR 1X10 2mm]
J7  Header_1x10  [J_HDR 1X10 2mm]
R22  value 240  [R_ARRAY-0402x4]  (hidden comment: Res_Net)

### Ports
XBee Data In (DI) (in), XBee Data Out (DO) (out), XBee ~{CTS} (~{CTS}) (bidir), XBee ~{RTS} (~{RTS}) (bidir)

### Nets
3.3V: J7.1 R22.5 R22.8
GND: J7.10
XBee ~{CTS} (~{CTS}): J6.9 ; port XBee ~{CTS} (~{CTS})
XBee Data In (DI): D8.2(Cathode) J7.3 ; port XBee Data In (DI)
XBee Data Out (DO): D9.2(Cathode) J7.2 ; port XBee Data Out (DO)
XBee ~{RTS} (~{RTS}): J6.5 ; port XBee ~{RTS} (~{RTS})
NetD8_1: D8.1(Anode) R22.1
NetD9_1: D9.1(Anode) R22.4

Not connected (* = marked no-connect by the designer): J6 1* 2* 3* 4* 6* 7* 8* 10*; J7 4* 5* 6* 7* 8* 9*; R22 2* 3* 6* 7*

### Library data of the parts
D8 = LED: Manufacturer_PN: LTST-C191KRKT; Parallax_PN: 350-10001; Syspro_Desc: LED 0603, Super Red Clear; Rotation_Offset: 180
D9 = LED: Manufacturer_PN: APT1608QBC/D; Parallax_PN: 350-10004; Syspro_Desc: LED 0603, Blue Clear; Rotation_Offset: 180
J6 J7 = Header_1x10: Header, 10-Pin; Manufacturer_PN: NPPN101BFCN-RC; Parallax_PN: 450-01701; Syspro_Desc: CON-SCKT,1X10,2mm,Straight,TH
R22 = Res_Net: as R17 on sheet Switch

## Sheet Headers.SchDoc
size Letter; SheetNumber: 5; SheetTotal: 14
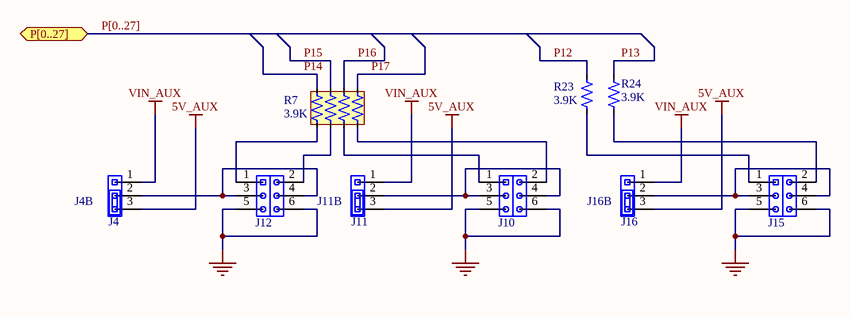
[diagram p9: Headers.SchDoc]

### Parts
J4  External Pwr/Cntrl Header  [J_HDR 1X3 2mm]  (value not drawn)
J4B  (no value)  (mechanical)
J10  Headers for selection jumpers  [J_HDR 2X3]  (value not drawn)
J11  External Pwr/Cntrl Header  [J_HDR 1X3 2mm]  (value not drawn)
J11B  (no value)  (mechanical)
J12  Headers for selection jumpers  [J_HDR 2X3]  (value not drawn)
J15  Headers for selection jumpers  [J_HDR 2X3]  (value not drawn)
J16  External Pwr/Cntrl Header  [J_HDR 1X3 2mm]  (value not drawn)
J16B  (no value)  (mechanical)
R7  value 3.9K  [R_ARRAY-0402x4]  (hidden comment: Res_Net)
R23  value 3.9K  [R/C_0402(1005)]  (hidden comment: Resistor)
R24  value 3.9K  [R/C_0402(1005)]  (hidden comment: Resistor)

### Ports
P[0..27] (bidir)

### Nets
5V_AUX: J4.3 J11.3 J16.3
GND: J10.5 J10.6 J12.5 J12.6 J15.5 J15.6
VIN_AUX: J4.1 J11.1 J16.1
P12: R23.1
P13: R24.1
P14: R7.4
P15: R7.3
P16: R7.2
P17: R7.1
NetJ4_2: J4.2 J12.3 J12.4
NetJ10_1: J10.1 R7.7
NetJ10_2: J10.2 R7.8
NetJ10_3: J10.3 J10.4 J11.2
NetJ12_1: J12.1 R7.5
NetJ12_2: J12.2 R7.6
NetJ15_1: J15.1 R23.2
NetJ15_2: J15.2 R24.2
NetJ15_3: J15.3 J15.4 J16.2

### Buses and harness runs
bus P[0..27] = port P[0..27]

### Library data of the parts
J4 J11 J16 = Header_1x03: Header, 1x3, Straight, 0.1"; Manufacturer_PN: 951103-8622-AR; Est_Cost: 0.039; Syspro_Desc: CON-HDR,1x3,0.1",Straight,TH; Parallax_PN: 451-01030
J4B J11B J16B = Jumper: Jumper, 0.1"; Manufacturer_PN: SPN02SYBN-RC; Parallax_PN: 452-00050; Syspro_Desc: CONN SHUNT 2MM OPEN TOP 2PS GO
J10 J12 J15 = Header_2x03: Header, 2x3, Straight, 0.1"; Manufacturer_PN: PBC03DAAN; Parallax_PN: 450-00105; Est_Cost: 0.090; Syspro_Desc: CON-HDR,2x3,0.1",Straight,TH
R7 = Res_Net: Resistor Network; Manufacturer_PN: CRA04S0833K90JTD; Syspro_Desc: RES-NTWK,3.9k,5%,0804; Parallax_PN: 179-10009
R23 R24 = Resistor: Manufacturer_PN: ERJ-2RKF3901X; Syspro_Desc: RES,3.9K,1%,0402; Parallax_PN: 150-12024

## Sheet Socket.SchDoc
size Letter; SheetNumber: 10; SheetTotal: 14
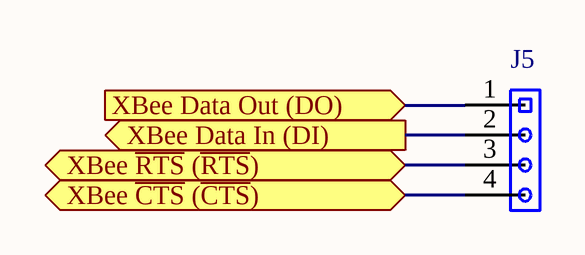
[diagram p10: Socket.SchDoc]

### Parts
J5  Header_1x04  [J_HDR 1X4]  (value not drawn)

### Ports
XBee Data In (DI) (out), XBee Data Out (DO) (in), XBee ~{CTS} (~{CTS}) (bidir), XBee ~{RTS} (~{RTS}) (bidir)

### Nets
XBee ~{CTS} (~{CTS}): J5.4 ; port XBee ~{CTS} (~{CTS})
XBee Data In (DI): J5.2 ; port XBee Data In (DI)
XBee Data Out (DO): J5.1 ; port XBee Data Out (DO)
XBee ~{RTS} (~{RTS}): J5.3 ; port XBee ~{RTS} (~{RTS})

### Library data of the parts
J5 = Header_1x04: Header, 1x4, Straight, 0.1"; Manufacturer_PN: 960104-6202-AR; Parallax_PN: 450-00401; Syspro_Desc: CON-SCKT,1x4,0.1",Straight,TH

## Sheet Breadboard.SchDoc
size Letter; SheetNumber: 3; SheetTotal: 14
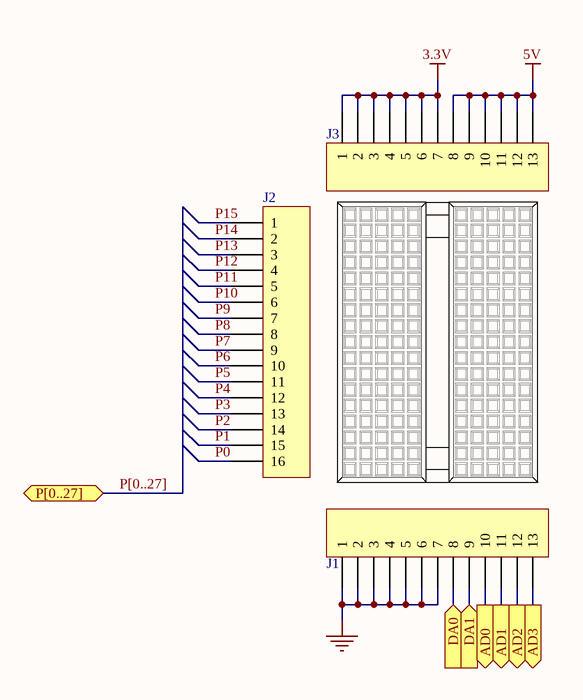
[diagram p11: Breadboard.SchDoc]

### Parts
Breadboard1  Breadboard  (value not drawn)
J1  Header_1x13  [J_HDR 1X13]  (value not drawn)
J2  Header_1x16  [J_HDR 1X16]  (value not drawn)
J3  Header_1x13  [J_HDR 1X13]  (value not drawn)

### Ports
AD0 (out), AD1 (out), AD2 (out), AD3 (out), DA0 (in), DA1 (in), P[0..27] (bidir)

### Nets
3.3V: J3.1 J3.2 J3.3 J3.4 J3.5 J3.6 J3.7
5V: J3.8 J3.9 J3.10 J3.11 J3.12 J3.13
GND: J1.1 J1.2 J1.3 J1.4 J1.5 J1.6 J1.7
AD0: J1.10 ; port AD0
AD1: J1.11 ; port AD1
AD2: J1.12 ; port AD2
AD3: J1.13 ; port AD3
DA0: J1.8 ; port DA0
DA1: J1.9 ; port DA1
P0: J2.16
P1: J2.15
P2: J2.14
P3: J2.13
P4: J2.12
P5: J2.11
P6: J2.10
P7: J2.9
P8: J2.8
P9: J2.7
P10: J2.6
P11: J2.5
P12: J2.4
P13: J2.3
P14: J2.2
P15: J2.1

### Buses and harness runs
bus P[0..27] = port P[0..27]

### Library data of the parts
Breadboard1 = Breadboard: Breadboard, Small; Parallax_PN: 700-00012
J1 J3 = Header_1x13: Header, 13-Pin; Manufacturer_PN: PPTC161LFBN-RC; Parallax_PN: 450-01301; Syspro_Desc: CON-SCKT,1x13,0.1",Straight,TH
J2 = Header_1x16: Header, 16-Pin; Manufacturer_PN: PPTC161LFBN-RC; Parallax_PN: 450-01601; Syspro_Desc: CON-SCKT,1x16,0.1",Straight,TH

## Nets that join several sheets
3.3V: Propeller (13 pins), Power (C16.2 VR2.OUT_1 VR2.OUT_2), USB (U4.5), DAC (U2.5), MicroSD (7 pins), XBee (J7.1 R22.5 R22.8), Breadboard (7 pins)
5V: Power (7 pins), Switch (R17.4), DAC (U3.8), ADC (FB1.1), Breadboard (6 pins)
5V_AUX: Power (Q3.3), Switch (R17.1), Headers (J4.3 J11.3 J16.3)
5V_USB: Power (C13.1 U5.5 U6.1), Switch (D5.2), USB (8 pins)
GND: Propeller Activity Board (MTG1.1 MTG2.1 MTG3.1 MTG4.1), Propeller (14 pins), Power (17 pins), Switch (D3.2 D4.2 SW1.2), USB (11 pins), DAC (9 pins), ADC (C1.2 C2.2 C3.1 U1.3), MicroSD (C10.2 J14.6 J14.13), XBee (J7.10), Headers (6 pins), Breadboard (7 pins)
VIN: Power (7 pins), Switch (D5.1)
VIN_AUX: Power (Q1.3), Headers (J4.1 J11.1 J16.1)
~{AUX_EN}: Power (Q2.1 Q5.1 R13.2), Switch (SW2.4)
AD0: ADC (U1.7), Breadboard (J1.10)
AD1: ADC (U1.6), Breadboard (J1.11)
AD2: ADC (U1.5), Breadboard (J1.12)
AD3: ADC (U1.4), Breadboard (J1.13)
DA0: DAC (C5.2 C9.1 U3.6 U3.7), Breadboard (J1.8)
DA1: DAC (C4.2 C8.2 U3.1 U3.2), Breadboard (J1.9)
P0: Propeller (U8.41), Breadboard (J2.16)
P1: Propeller (U8.42), Breadboard (J2.15)
P2: Propeller (U8.43), Breadboard (J2.14)
P3: Propeller (U8.44), Breadboard (J2.13)
P4: Propeller (U8.1), Breadboard (J2.12)
P5: Propeller (U8.2), Breadboard (J2.11)
P6: Propeller (U8.3), Breadboard (J2.10)
P7: Propeller (U8.4), Breadboard (J2.9)
P8: Propeller (U8.9), Breadboard (J2.8)
P9: Propeller (U8.10), Breadboard (J2.7)
P10: Propeller (U8.11), Breadboard (J2.6)
P11: Propeller (U8.12), Breadboard (J2.5)
P12: Propeller (U8.13), Headers (R23.1), Breadboard (J2.4)
P13: Propeller (U8.14), Headers (R24.1), Breadboard (J2.3)
P14: Propeller (U8.15), Headers (R7.4), Breadboard (J2.2)
P15: Propeller (U8.16), Headers (R7.3), Breadboard (J2.1)
P16: Propeller (U8.19), Headers (R7.2)
P17: Propeller (U8.20), Headers (R7.1)
P18: Propeller (U8.21), ADC (U1.8)
P19: Propeller (U8.22), ADC (U1.9)
P20: Propeller (U8.23), ADC (U1.10)
P21: Propeller (U8.24), ADC (U1.1)
P22: Propeller (U8.25), MicroSD (J14.7 R9.6)
P23: Propeller (U8.26), MicroSD (J14.5)
P24: Propeller (U8.31), MicroSD (J14.3 R8.5)
P25: Propeller (U8.32), MicroSD (J14.2 R9.7)
P26: Propeller (U8.33), DAC (R1.1 R4.2 U2.1)
P27: Propeller (U8.34), DAC (R1.4 R3.2 U2.3)
~{PWR_EN}: Power (R10.2), Switch (SW2.1)
Propeller ~{Reset} (~{RST}): Propeller (U8.7), Switch (SW1.1), USB (Q4.C)
Serial/USB RX: Propeller (U8.38), USB (U4.4)
Serial/USB TX: Propeller (R16.6 U8.37), USB (U9.4)
~{USB_PWR_EN}: Power (U5.1), USB (C27.1 R21.6)
XBee ~{CTS} (~{CTS}): XBee (J6.9), Socket (J5.4)
XBee Data In (DI): XBee (D8.2 J7.3), Socket (J5.2)
XBee Data Out (DO): XBee (D9.2 J7.2), Socket (J5.1)
XBee ~{RTS} (~{RTS}): XBee (J6.5), Socket (J5.3)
